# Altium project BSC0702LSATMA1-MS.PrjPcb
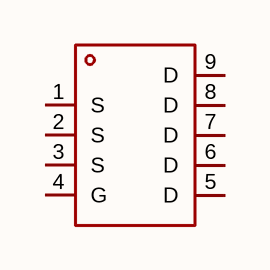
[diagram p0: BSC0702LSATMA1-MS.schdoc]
1 sheet, 1 parts. Net scope: global (net labels, ports and power ports of the same name join across sheets).

## Sheet BSC0702LSATMA1-MS.schdoc
size 127 x 101 mm

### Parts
Q?  bsc0702lsatma1-ms  [PDFN-8_L4.9-W5.8-P1.27-LS6.1-BL]  (value not drawn)

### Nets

Not connected (* = marked no-connect by the designer): Q? 1(S) 2(S) 3(S) 4(G) 5(D) 6(D) 7(D) 8(D) 9(D)

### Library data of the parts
Q? = bsc0702lsatma1-ms: 数量:1个N沟道;漏源电压(Vdss):60V;连续漏极电流(Id):125A;导通电阻(RDS(on)):2.4mΩ@10V;耗散功率(Pd):113W;阈值电压(Vgs(th)):1.6V;; Manufacturer: MSKSEMI(美森科); AddInBom: yes; ModelId: 178189b27e7544aca50c111426555358; ModelName: PDFN-8_L4.9-W5.8-H1.0-P1.27; ModelTransform: 200.787,240.157,0,0,0,0,-0.097,0,0; Number: 1个N沟道; Drain to Source Voltage: 60V; Current - Continuous Drain(Id): 125A; Pd - Power Dissipation: 113W; Gate Threshold Voltage (Vgs(th)): 1.6V; Gate Charge(Qg): 74.37nC; Input Capacitance(Ciss): 4.61nF; Reverse Transfer Capacitance (Crss@Vds): 66pF; Type: N沟道; Output Capacitance(Coss): 2.188nF; Vgs: ±20V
